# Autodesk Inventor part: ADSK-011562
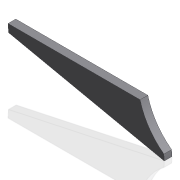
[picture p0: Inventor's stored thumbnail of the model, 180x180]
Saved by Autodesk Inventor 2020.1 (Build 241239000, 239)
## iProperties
Created: 2000-02
Part Number: ADSK-011562
Material: Pearson HRS
Document SubType Name: Modeling
Designer: sspink
Density: 7.83 g/cm^3
Appearance: Métal - Acier
Mass: 93.3191 g
Surface Area: 56.0422 cm^2
Volume: 11.9181 cm^3
Control State: 0
Checked Out: False
Master: False
Shininess: 0.0
Length Units: 11269
Angle Units: 11279
Time Units: 11290
Mass Units: 11283
Length Display Precision: 3
Angle Display Precision: 2
Compacted: True
Dimensions: 32x6x122 mm
Mass: 0,093 kg
VLT_Material: Pearson HRS
Density: 0.0
Volumn: 0.0
Area: 0.0
PropertySet Name: Model Information
Author: sspink
Revision Number: -
Title: ADSK-011562
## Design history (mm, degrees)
node "Solide1"
  node "Extrusion1" dims "d8" = 6, "d9" = 0
sketch "Sketch1"
  geometry: L1 (0, 0)-(-103.164, 0); L2 (18.836, -32)-(18.58, -27.464); L3 (-103.164, 0)-(-102.826, -5.99); L4 (-102.826, -5.99)-(18.836, -32); A1 r 50 centre (48.36, 12.7) between (0, 0) and (18.58, -27.464)
  constraints: 8 end point, 2 point on circle, 1 centre point, 1 horizontal, 1 parallel
  dimensions: "d0" = 12.7 distance from line of A1.centre L1; "d1" = 100 diameter of A1; "d3" = 120 distance between parallel lines of L2 L3; "d4" = 32 distance from line of L2.start L1; "d5" = 152 distance from line of A1.centre L3; "d6" = 6 distance of L1.end L3.end; "d7" = 103 distance from line of L1.start L3
node "Corps solides"
node "Corps surfaciques"
